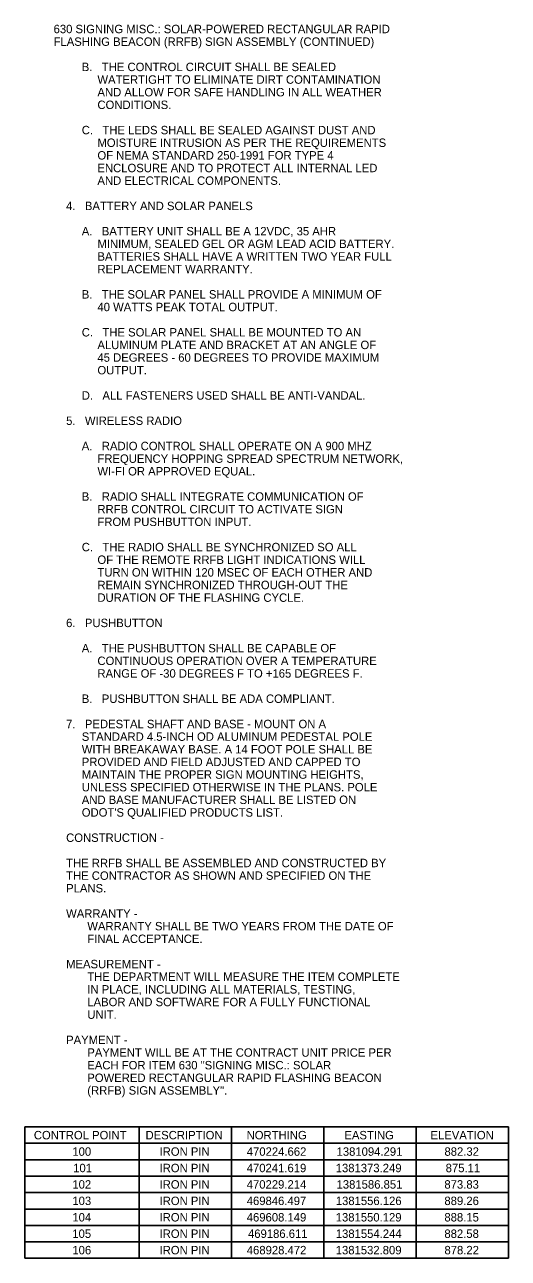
# Model space of a CAD drawing. Extents: x -8.5 to 44.5, y -22.3 to 22.
# Drawn here: x 24.02 to 32.05, y -22.26 to -1.76 of the extents above; entities that cross this region are included whole.
import ezdxf

# ---------------------------------------------------------------- set-up
doc = ezdxf.new("R2010")
doc.units = 0
doc.layers.add('SV_X_Random_Point', color=7, linetype='Continuous')

msp = doc.modelspace()

# ---------------------------------------------------------------- linework, layer by layer
at = {"layer": 'SV_X_Random_Point'}
for p, q in [((24.02, -20.073), (32.053, -20.073)), ((24.02, -20.073), (24.02, -22.257)), ((25.921, -20.073), (25.921, -22.257)), ((27.453, -20.073), (27.453, -22.257)), ((28.986, -20.073), (28.986, -22.257)), ((30.52, -20.073), (30.52, -22.257)), ((32.053, -20.073), (32.053, -22.257)), ((24.02, -20.346), (32.053, -20.346)), ((24.02, -20.619), (32.053, -20.619)), ((24.02, -20.892), (32.053, -20.892)), ((24.02, -21.165), (32.053, -21.165)), ((24.02, -21.438), (32.053, -21.438)), ((24.02, -21.711), (32.053, -21.711)), ((24.02, -21.984), (32.053, -21.984)), ((24.02, -22.257), (32.053, -22.257))]:
    msp.add_line(p, q, dxfattribs=at)

# ---------------------------------------------------------------- texts
for s, p in [('630 SIGNING MISC.: SOLAR-POWERED RECTANGULAR RAPID', (24.5, -1.897)), ('FLASHING BEACON (RRFB) SIGN ASSEMBLY (CONTINUED)', (24.5, -2.107)), ('         B.   THE CONTROL CIRCUIT SHALL BE SEALED', (24.5, -2.527)), ('              WATERTIGHT TO ELIMINATE DIRT CONTAMINATION', (24.5, -2.737)), ('              AND ALLOW FOR SAFE HANDLING IN ALL WEATHER', (24.5, -2.947)), ('              CONDITIONS.', (24.5, -3.157)), ('         C.   THE LEDS SHALL BE SEALED AGAINST DUST AND', (24.5, -3.577)), ('              MOISTURE INTRUSION AS PER THE REQUIREMENTS', (24.5, -3.787)), ('              OF NEMA STANDARD 250-1991 FOR TYPE 4', (24.5, -3.997)), ('              ENCLOSURE AND TO PROTECT ALL INTERNAL LED', (24.5, -4.207)), ('              AND ELECTRICAL COMPONENTS.', (24.5, -4.417)), ('    4.   BATTERY AND SOLAR PANELS', (24.5, -4.837)), ('         A.   BATTERY UNIT SHALL BE A 12VDC, 35 AHR', (24.5, -5.257)), ('              MINIMUM, SEALED GEL OR AGM LEAD ACID BATTERY.', (24.5, -5.467)), ('              BATTERIES SHALL HAVE A WRITTEN TWO YEAR FULL', (24.5, -5.677)), ('              REPLACEMENT WARRANTY.', (24.5, -5.887)), ('         B.   THE SOLAR PANEL SHALL PROVIDE A MINIMUM OF', (24.5, -6.307)), ('              40 WATTS PEAK TOTAL OUTPUT.', (24.5, -6.517)), ('         C.   THE SOLAR PANEL SHALL BE MOUNTED TO AN', (24.5, -6.937)), ('              ALUMINUM PLATE AND BRACKET AT AN ANGLE OF', (24.5, -7.147)), ('              45 DEGREES - 60 DEGREES TO PROVIDE MAXIMUM', (24.5, -7.357)), ('              OUTPUT.', (24.5, -7.567)), ('         D.   ALL FASTENERS USED SHALL BE ANTI-VANDAL.', (24.5, -7.987)), ('    5.   WIRELESS RADIO', (24.5, -8.407)), ('         A.   RADIO CONTROL SHALL OPERATE ON A 900 MHZ', (24.5, -8.827)), ('              FREQUENCY HOPPING SPREAD SPECTRUM NETWORK,', (24.5, -9.037)), ('              WI-FI OR APPROVED EQUAL.', (24.5, -9.247)), ('         B.   RADIO SHALL INTEGRATE COMMUNICATION OF', (24.5, -9.667)), ('              RRFB CONTROL CIRCUIT TO ACTIVATE SIGN', (24.5, -9.877)), ('              FROM PUSHBUTTON INPUT.', (24.5, -10.087)), ('         C.   THE RADIO SHALL BE SYNCHRONIZED SO ALL', (24.5, -10.507)), ('              OF THE REMOTE RRFB LIGHT INDICATIONS WILL', (24.5, -10.717)), ('              TURN ON WITHIN 120 MSEC OF EACH OTHER AND', (24.5, -10.927)), ('              REMAIN SYNCHRONIZED THROUGH-OUT THE', (24.5, -11.137)), ('              DURATION OF THE FLASHING CYCLE.', (24.5, -11.347)), ('    6.   PUSHBUTTON', (24.5, -11.767)), ('         A.   THE PUSHBUTTON SHALL BE CAPABLE OF', (24.5, -12.187)), ('              CONTINUOUS OPERATION OVER A TEMPERATURE', (24.5, -12.397)), ('              RANGE OF -30 DEGREES F TO +165 DEGREES F.', (24.5, -12.607)), ('         B.   PUSHBUTTON SHALL BE ADA COMPLIANT.', (24.5, -13.027)), ('    7.   PEDESTAL SHAFT AND BASE - MOUNT ON A', (24.5, -13.447)), ('         STANDARD 4.5-INCH OD ALUMINUM PEDESTAL POLE', (24.5, -13.657)), ('         WITH BREAKAWAY BASE. A 14 FOOT POLE SHALL BE', (24.5, -13.867)), ('         PROVIDED AND FIELD ADJUSTED AND CAPPED TO', (24.5, -14.077)), ('         MAINTAIN THE PROPER SIGN MOUNTING HEIGHTS,', (24.5, -14.287)), ('         UNLESS SPECIFIED OTHERWISE IN THE PLANS. POLE', (24.5, -14.497)), ('         AND BASE MANUFACTURER SHALL BE LISTED ON', (24.5, -14.707)), ("         ODOT'S QUALIFIED PRODUCTS LIST.", (24.5, -14.917)), ('    CONSTRUCTION -', (24.5, -15.337)), ('    THE RRFB SHALL BE ASSEMBLED AND CONSTRUCTED BY', (24.5, -15.757)), ('    THE CONTRACTOR AS SHOWN AND SPECIFIED ON THE', (24.5, -15.967)), ('    PLANS.', (24.5, -16.177)), ('    WARRANTY -', (24.5, -16.597)), ('WARRANTY SHALL BE TWO YEARS FROM THE DATE OF', (25.06, -16.807)), ('FINAL ACCEPTANCE.', (25.06, -17.017)), ('    MEASUREMENT -', (24.5, -17.437)), ('THE DEPARTMENT WILL MEASURE THE ITEM COMPLETE', (25.06, -17.647)), ('IN PLACE, INCLUDING ALL MATERIALS, TESTING,', (25.06, -17.857)), ('LABOR AND SOFTWARE FOR A FULLY FUNCTIONAL', (25.06, -18.067)), ('UNIT.', (25.06, -18.277)), ('    PAYMENT -', (24.5, -18.697)), ('PAYMENT WILL BE AT THE CONTRACT UNIT PRICE PER', (25.06, -18.907)), ('EACH FOR ITEM 630 "SIGNING MISC.: SOLAR', (25.06, -19.117)), ('POWERED RECTANGULAR RAPID FLASHING BEACON', (25.06, -19.327)), ('(RRFB) SIGN ASSEMBLY".', (25.06, -19.537)), ('CONTROL POINT', (24.172, -20.28)), ('DESCRIPTION', (26.027, -20.28)), ('NORTHING', (27.706, -20.28)), ('EASTING', (29.33, -20.28)), ('ELEVATION', (30.76, -20.28)), ('100', (24.812, -20.553)), ('IRON PIN', (26.26, -20.553)), ('470224.662', (27.709, -20.553)), ('1381094.291', (29.2, -20.553)), ('882.32', (30.992, -20.553)), ('101', (24.825, -20.826)), ('IRON PIN', (26.26, -20.826)), ('470241.619', (27.708, -20.826)), ('1381373.249', (29.186, -20.826)), ('875.11', (31.012, -20.826)), ('102', (24.812, -21.099)), ('IRON PIN', (26.26, -21.099)), ('470229.214', (27.708, -21.099)), ('1381586.851', (29.2, -21.099)), ('873.83', (30.991, -21.099)), ('103', (24.812, -21.372)), ('IRON PIN', (26.26, -21.372)), ('469846.497', (27.708, -21.372)), ('1381556.126', (29.187, -21.372)), ('889.26', (30.991, -21.372)), ('104', (24.812, -21.645)), ('IRON PIN', (26.26, -21.645)), ('469608.149', (27.708, -21.645)), ('1381550.129', (29.186, -21.645)), ('888.15', (30.991, -21.645)), ('105', (24.811, -21.918)), ('IRON PIN', (26.26, -21.918)), ('469186.611', (27.729, -21.918)), ('1381554.244', (29.187, -21.918)), ('882.58', (30.991, -21.918)), ('106', (24.812, -22.191)), ('IRON PIN', (26.26, -22.191)), ('468928.472', (27.709, -22.191)), ('1381532.809', (29.186, -22.191)), ('878.22', (30.992, -22.191))]:
    msp.add_text(s, height=0.14, dxfattribs=at).set_placement(p)

doc.saveas('drawing.dxf')
